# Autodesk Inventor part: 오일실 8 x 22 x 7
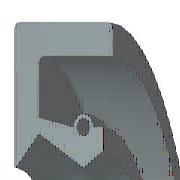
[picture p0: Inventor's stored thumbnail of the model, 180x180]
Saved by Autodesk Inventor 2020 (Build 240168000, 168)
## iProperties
IsCustomPart: 1
Created: 2012-02
Part Number: 오일실 8 x 22 x 7
Material: 고무
Description: 오일-실
Document SubType Name: Modeling
Standard: KS B 2804
Designer: mduedu
Standards Organization: KS
Language: ko-KR
Size Designation: D - 8 22 7
Categories: <MemberInstance><Categories><Category DisplayName="샤프트 부품" InternalName="7f7aeb1f-a693-4053-b835-cee3144e0d98" Mnemonic="SHFT"><Category DisplayName="실링" Intern
Density: 0.93 g/cm^3
Mass: 1.28441 g
Surface Area: 18.2787 cm^2
Volume: 1.38108 cm^3
Appearance: 고무 - 검은색 - 버전 1.1
Author: mduedu
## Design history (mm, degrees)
revolve "본체" stored, may be unused: angle "d17" = 90 deg
revolve "스프링1" stored, may be unused: angle "d18" = 90 deg
body "Solid1"
sketch "스케치1"
  geometry: L1 (0, 11)-(7, 11); L2 (7, 9.25)-(1.75, 9.25); L3 (1.75, 5.75)-(4.9, 4); L4 (4.9, 4)-(0, 4); L5 (0, 0)-(9.586, 0) reference; L6 (4.9, 4)-(6.3, 4.875); L7 (0, 18)-(0, -3) reference; L8 (-1.941, 0)-(11.507, 0) reference; L9 (4.2, 6.1)-(1.75, 6.59); L10 (1.75, 6.59)-(1.75, 9.25); L11 (0, 11)-(0, 4.088); L12 (4.9, 4)-(0, 4); L13 (1.75, 5.75)-(0.152, 4.028); L14 (7, 11)-(7, 9.25); L15 (5.6, 6.1)-(6.3, 6.1); L16 (6.3, 6.1)-(6.3, 4.875); C1 r 0.455 at (4.9, 6.1); A1 r 0.7 centre (4.9, 6.1) between (5.6, 6.1) and (4.2, 6.1); A2 r 0.088 centre (0.088, 4.088) between (0, 4.088) and (0.152, 4.028); 1 further point
  constraints: 28 end point, 5 horizontal alignment, 5 point on line, 4 point on circle, 4 vertical alignment, 3 centre point, 3 tangent, 2 collinear, 2 horizontal, 2 perpendicular, 1 coincident, 1 parallel
  dimensions: "d0" = 22 diameter of L1 L5 (= SD2); "d1" = 1.75 distance of L1.end L2.start (= SD); "d2" = 0.91 diameter of C1 (= SPDI); "d3" = 1.4 diameter of A1 (= SPDA); "d4" = 8 diameter of L3.end L5 (= NND); "d5" = 11.5 diameter of L3.start L5 (= TKDM); "d7" = 13.18 diameter of L9.end L5 (= TKDM + 0.24 x SWDT); "d8" = 1.75 distance between parallel lines of L11 L10 (= SD); "d9" = 4.9 distance from line of L11 C1.centre (= SPDST); "d10" = 12.2 diameter of C1.centre L5 (= HLDM); "d11" = 0.0875 radius of A2 (= 0.25 x LAB); "d12" = 6.3 distance between parallel lines of L11 L16 (= SDI); "d13" = 9.75 diameter of L6.end L5 (= ABDM); "d14" = 7 distance from line of L11 L1.end (= SWDT)
fillet "모깎기1" dims "d6" = 0.3 (= RR)
other parameters: "SD2" = 22 [user parameter; used in 1 equation term], "SWDT" = 7 [user parameter; used in 2 equation terms], "RR" = 0.3 [user parameter; used in 1 equation term], "SD" = 1.75 [user parameter; used in 2 equation terms], "NND" = 8 [user parameter; used in 1 equation term], "SPDA" = 1.4 [user parameter; used in 1 equation term], "SPDI" = 0.91 [user parameter; used in 1 equation term], "TKDM" = 11.5 [user parameter; used in 2 equation terms], "HLDM" = 12.2 [user parameter; used in 1 equation term], "ABDM" = 9.75 [user parameter; used in 1 equation term], "SDI" = 6.3 [user parameter; used in 1 equation term], "SPDST" = 4.9 [user parameter; used in 1 equation term], "LAB" = 0.35 [user parameter; used in 1 equation term], "d15" = 0, "d16" = 0, "d19" = 0
